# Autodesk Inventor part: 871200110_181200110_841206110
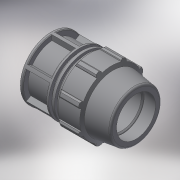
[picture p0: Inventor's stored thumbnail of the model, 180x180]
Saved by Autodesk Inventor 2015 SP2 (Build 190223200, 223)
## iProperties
Created: 2017-02
Part Number: 871200110_181200110_841206110
Material: Generic
Description: PLASSON END PLUG 110
Document SubType Name: Modeling
Designer: KIM
Mass: 947.017 g
Surface Area: 1382.98 cm^2
Volume: 947.017 cm^3
Density: 1 g/cm^3
Appearance: Default
Author: Кирилл
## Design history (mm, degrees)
derived "87120.ipt"
feature "Solid1::87120.ipt"
tag "TaggingFeature1"
body "Solid1"
other parameters: "d4" = 33.42857, "d5" = 58.5, "d7" = 181, "d8" = 135.75, "d9" = 33.42857, "d11" = 6.68571, "d12" = 144.8, "d13" = 120 deg, "d14" = 143, "d15" = 8 deg, "d16" = 162.9, "d18" = 5.5, "d19" = 35 deg, "d20" = 17.5 deg, "d21" = 168.33, "d23" = 0, "d25" = 360 deg, "d27" = 3.62, "d34" = 9.05, "d36" = 0, "d42" = 58.5, "d43" = 5.43, "d46" = 3.3, "d53" = 2.2, "d55" = 360 deg, "d59" = 58.5, "d64" = 234, "d66" = 23.53, "d67" = 14.48, "d68" = 221, "d70" = 26.74286, "d71" = 6.68571, "d72" = 159.642, "d75" = 13.37143, "E_" = 181, "H_" = 234, "l_" = 221
